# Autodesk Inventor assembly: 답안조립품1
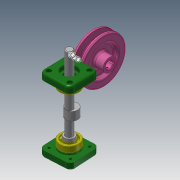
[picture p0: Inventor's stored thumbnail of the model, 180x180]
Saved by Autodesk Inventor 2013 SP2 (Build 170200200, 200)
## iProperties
Created: 2021-08
Part Number: 답안조립품1
Document SubType Name: Assembly
Designer: kumcom17
Author: kumcom17
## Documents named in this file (8)
- C:\Users\kumcom17\Desktop\710806V1005\답안조립품1.iam
- C:\Users\kumcom17\Desktop\710806V1005\본체.ipt
- C:\Users\kumcom17\Desktop\710806V1005\앞커버.ipt
- C:\Users\kumcom17\Desktop\710806V1005\뒤커버.ipt
- C:\Users\kumcom17\Desktop\710806V1005\베어링 12x32x10.ipt
- C:\Users\kumcom17\Desktop\710806V1005\편심축.ipt
- C:\Users\kumcom17\Desktop\710806V1005\키 4x4x10.ipt
- C:\Users\kumcom17\Desktop\710806V1005\V벨트풀리.ipt
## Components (1 placed, 1 different names)
1. V벨트풀리:1
